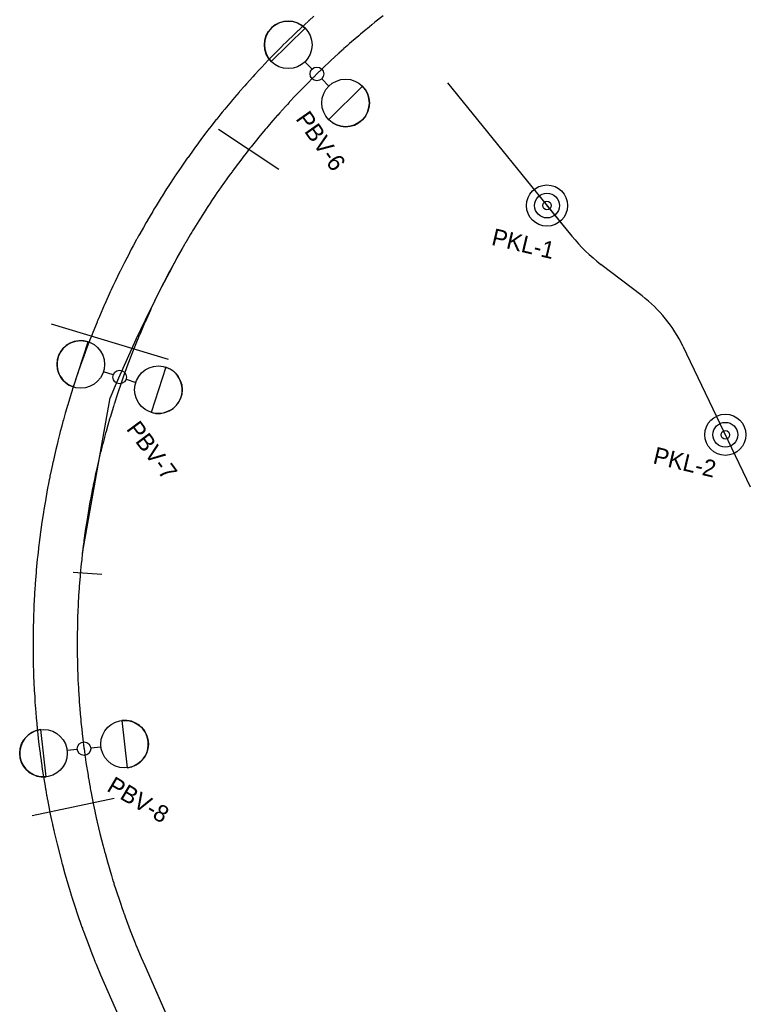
# Model space of a CAD drawing. Extents: x 0 to 511877, y 0 to 6211921.
# Drawn here: x 511553.8 to 511607.5, y 6211602.9 to 6211675.4 of the extents above; entities that cross this region are included whole.
import ezdxf

# ---------------------------------------------------------------- set-up
doc = ezdxf.new("R2010")
doc.units = 0
for name, color, linetype in [('Help', 7, 'Continuous'), ('TV_U_LYS_iWay', 7, 'Continuous'), ('TV_U_LYS_Ledn-', 7, 'Continuous'), ('TV_U_LYS_Ledn-ror', 7, 'Continuous'), ('TV_U_LYS_Mastenummer', 7, 'Continuous'), ('TV_U_LYS_Nyx330-Boligvej', 7, 'Continuous')]:
    doc.layers.add(name, color=color, linetype=linetype)

msp = doc.modelspace()

# ---------------------------------------------------------------- linework, layer by layer
at = {"layer": 'Help'}
for p, q in [((511585.237, 6211670.727), (511594.372, 6211659.463)), ((511568.38, 6211667.325), (511572.834, 6211664.395)), ((511556.075, 6211653.009), (511564.682, 6211650.411)), ((511602.55, 6211651.353), (511607.508, 6211641.01)), ((511557.697, 6211634.727), (511559.814, 6211634.593)), ((511554.669, 6211616.839), (511560.705, 6211618.102))]:
    msp.add_line(p, q, dxfattribs=at)
for points in [[(511575.406, 6211675.638), (511575.056, 6211675.322), (511575.042, 6211675.31), (511574.995, 6211675.268), (511574.469, 6211674.783), (511574.267, 6211674.594), (511574.219, 6211674.549), (511574.006, 6211674.346), (511573.83, 6211674.179), (511573.546, 6211673.904), (511573.506, 6211673.866), (511573.405, 6211673.767), (511573.104, 6211673.471), (511573.058, 6211673.426), (511572.617, 6211672.983), (511572.558, 6211672.923), (511572.405, 6211672.767), (511572.041, 6211672.392), (511571.827, 6211672.168), (511571.703, 6211672.037), (511571.665, 6211671.997), (511571.237, 6211671.539), (511571.199, 6211671.498), (511571.056, 6211671.343), (511570.915, 6211671.188), (511570.446, 6211670.668), (511570.315, 6211670.521), (511570.295, 6211670.498), (511569.942, 6211670.095), (511569.905, 6211670.053), (511569.566, 6211669.658), (511569.441, 6211669.511), (511569.414, 6211669.479), (511569.341, 6211669.393), (511568.844, 6211668.796), (511568.662, 6211668.574), (511568.56, 6211668.448), (511568.253, 6211668.066), (511568.226, 6211668.032), (511568.128, 6211667.908), (511567.85, 6211667.555), (511567.734, 6211667.405), (511567.708, 6211667.371), (511567.438, 6211667.02), (511567.087, 6211666.555), (511566.79, 6211666.156), (511566.762, 6211666.117), (511566.646, 6211665.958), (511566.623, 6211665.927), (511566.416, 6211665.641), (511566.119, 6211665.225), (511566.105, 6211665.205), (511566.092, 6211665.186), (511565.743, 6211664.687), (511565.592, 6211664.467), (511565.459, 6211664.273), (511565.132, 6211663.786), (511565.113, 6211663.758), (511565.112, 6211663.755), (511565.06, 6211663.678), (511564.837, 6211663.339), (511564.594, 6211662.964), (511564.571, 6211662.929), (511564.235, 6211662.399), (511564.176, 6211662.305), (511563.79, 6211661.68), (511563.702, 6211661.535), (511563.69, 6211661.515), (511563.639, 6211661.43), (511563.544, 6211661.272), (511563.17, 6211660.638), (511563.153, 6211660.609), (511563.064, 6211660.456), (511562.859, 6211660.099), (511562.588, 6211659.618), (511562.51, 6211659.477), (511562.373, 6211659.228), (511562.359, 6211659.203), (511562.104, 6211658.733), (511561.973, 6211658.488), (511561.841, 6211658.236), (511561.829, 6211658.214), (511561.631, 6211657.833), (511561.467, 6211657.513), (511561.449, 6211657.477), (511561.144, 6211656.868), (511561.131, 6211656.842), (511560.953, 6211656.478), (511560.775, 6211656.107), (511560.622, 6211655.783), (511560.614, 6211655.766), (511560.497, 6211655.515), (511560.47, 6211655.458), (511560.419, 6211655.348), (511560.016, 6211654.453), (511560.007, 6211654.433), (511560, 6211654.416), (511559.626, 6211653.548), (511559.573, 6211653.424), (511559.561, 6211653.394), (511559.51, 6211653.272), (511559.507, 6211653.266), (511559.471, 6211653.179), (511559.451, 6211653.131), (511559.138, 6211652.36), (511558.987, 6211651.977), (511558.98, 6211651.959), (511558.73, 6211651.307), (511558.601, 6211650.961), (511558.519, 6211650.739), (511558.511, 6211650.718), (511558.51, 6211650.715), (511558.496, 6211650.676), (511558.338, 6211650.237), (511558.073, 6211649.479), (511558.065, 6211649.456), (511557.97, 6211649.175), (511557.816, 6211648.709), (511557.681, 6211648.294), (511557.629, 6211648.13), (511557.626, 6211648.119), (511557.621, 6211648.103), (511557.552, 6211647.885), (511557.296, 6211647.041), (511557.262, 6211646.927), (511557.256, 6211646.908), (511557.118, 6211646.429), (511556.983, 6211645.95), (511556.945, 6211645.81), (511556.863, 6211645.507), (511556.856, 6211645.482), (511556.748, 6211645.074), (511556.69, 6211644.85), (511556.567, 6211644.364), (511556.561, 6211644.337), (511556.508, 6211644.122), (511556.42, 6211643.759), (511556.315, 6211643.31), (511556.213, 6211642.856), (511556.207, 6211642.828), (511556.169, 6211642.657), (511556.074, 6211642.216), (511555.989, 6211641.805), (511555.98, 6211641.762), (511555.976, 6211641.739), (511555.943, 6211641.577), (511555.939, 6211641.556), (511555.902, 6211641.367), (511555.791, 6211640.791), (511555.729, 6211640.452), (511555.68, 6211640.179), (511555.673, 6211640.139), (511555.559, 6211639.464), (511555.539, 6211639.342), (511555.538, 6211639.334), (511555.509, 6211639.152), (511555.502, 6211639.11), (511555.374, 6211638.264), (511555.367, 6211638.213), (511555.269, 6211637.497), (511555.262, 6211637.451), (511555.219, 6211637.114), (511555.216, 6211637.085), (511555.15, 6211636.535), (511555.145, 6211636.496), (511555.139, 6211636.438), (511555.09, 6211635.991), (511555.058, 6211635.692), (511554.981, 6211634.88), (511554.973, 6211634.788), (511554.97, 6211634.753), (511554.967, 6211634.711), (511554.903, 6211633.909), (511554.9, 6211633.86), (511554.891, 6211633.741), (511554.878, 6211633.543), (511554.853, 6211633.148), (511554.824, 6211632.622), (511554.81, 6211632.346), (511554.798, 6211632.091), (511554.796, 6211632.04), (511554.776, 6211631.497), (511554.769, 6211631.269), (511554.767, 6211631.218), (511554.753, 6211630.66), (511554.752, 6211630.597), (511554.748, 6211630.362), (511554.743, 6211629.96), (511554.741, 6211629.401), (511554.741, 6211629.347), (511554.741, 6211629.23), (511554.745, 6211628.718), (511554.746, 6211628.643), (511554.747, 6211628.591), (511554.755, 6211628.117), (511554.756, 6211628.053), (511554.763, 6211627.767), (511554.769, 6211627.573), (511554.789, 6211626.989), (511554.801, 6211626.711), (511554.803, 6211626.649), (511554.834, 6211626.04), (511554.837, 6211625.981), (511554.844, 6211625.854), (511554.864, 6211625.525), (511554.886, 6211625.199), (511554.907, 6211624.901), (511554.92, 6211624.724), (511554.975, 6211624.05), (511554.981, 6211623.981), (511555.014, 6211623.613), (511555.031, 6211623.437), (511555.037, 6211623.378), (511555.074, 6211623.013), (511555.094, 6211622.822), (511555.131, 6211622.486), (511555.181, 6211622.052), (511555.262, 6211621.405), (511555.267, 6211621.369), (511555.272, 6211621.33), (511555.335, 6211620.869), (511555.344, 6211620.803), (511555.384, 6211620.52), (511555.394, 6211620.457), (511555.426, 6211620.239), (511555.58, 6211619.262), (511555.601, 6211619.135), (511555.662, 6211618.782), (511555.674, 6211618.711), (511555.744, 6211618.323), (511555.756, 6211618.257), (511555.783, 6211618.11), (511555.794, 6211618.049), (511555.801, 6211618.011), (511556.013, 6211616.935), (511556.108, 6211616.479), (511556.169, 6211616.197), (511556.184, 6211616.13), (511556.196, 6211616.074), (511556.252, 6211615.826), (511556.256, 6211615.804), (511556.263, 6211615.773), (511556.271, 6211615.741), (511556.303, 6211615.599), (511556.51, 6211614.723), (511556.752, 6211613.766), (511556.783, 6211613.649), (511556.787, 6211613.631), (511556.801, 6211613.581), (511556.833, 6211613.459), (511556.867, 6211613.33), (511556.885, 6211613.265), (511556.903, 6211613.199), (511557.086, 6211612.537), (511557.397, 6211611.476), (511557.49, 6211611.172), (511557.498, 6211611.145), (511557.519, 6211611.079), (511557.52, 6211611.074), (511557.575, 6211610.897), (511557.591, 6211610.847), (511557.599, 6211610.821), (511557.741, 6211610.376), (511558.09, 6211609.328), (511558.236, 6211608.907), (511558.311, 6211608.694), (511558.337, 6211608.621), (511558.371, 6211608.526), (511558.378, 6211608.506), (511558.394, 6211608.461), (511558.403, 6211608.435), (511558.474, 6211608.239), (511558.86, 6211607.207), (511559.068, 6211606.673), (511559.218, 6211606.295), (511559.236, 6211606.25), (511559.25, 6211606.217), (511559.27, 6211606.168), (511559.277, 6211606.149), (511559.299, 6211606.095), (511559.381, 6211605.895), (511559.709, 6211605.111), (511559.982, 6211604.481), (511564.929, 6211593.23)], [(511580.498, 6211675.666), (511579.899, 6211675.191), (511579.665, 6211675.001), (511579.658, 6211674.995), (511579.483, 6211674.852), (511579.441, 6211674.818), (511579.135, 6211674.565), (511579.092, 6211674.529), (511578.843, 6211674.319), (511578.698, 6211674.197), (511578.168, 6211673.741), (511578.032, 6211673.622), (511577.842, 6211673.455), (511577.615, 6211673.253), (511577.576, 6211673.219), (511577.236, 6211672.913), (511577.228, 6211672.905), (511577.19, 6211672.87), (511576.681, 6211672.401), (511576.492, 6211672.224), (511576.45, 6211672.185), (511576.245, 6211671.991), (511576.081, 6211671.834), (511575.807, 6211671.57), (511575.773, 6211671.537), (511575.679, 6211671.446), (511575.388, 6211671.159), (511575.353, 6211671.124), (511574.925, 6211670.695), (511574.875, 6211670.645), (511574.732, 6211670.498), (511574.382, 6211670.138), (511574.18, 6211669.926), (511574.063, 6211669.803), (511574.033, 6211669.771), (511573.617, 6211669.326), (511573.587, 6211669.294), (511573.451, 6211669.145), (511573.321, 6211669.004), (511572.869, 6211668.502), (511572.748, 6211668.365), (511572.734, 6211668.35), (511572.391, 6211667.958), (511572.364, 6211667.928), (511572.036, 6211667.546), (511571.919, 6211667.409), (511571.895, 6211667.38), (511571.831, 6211667.305), (511571.351, 6211666.728), (511571.182, 6211666.521), (511571.088, 6211666.406), (511570.791, 6211666.036), (511570.77, 6211666.009), (511570.678, 6211665.894), (511570.411, 6211665.554), (511570.302, 6211665.413), (511570.281, 6211665.386), (511570.023, 6211665.051), (511569.689, 6211664.608), (511569.405, 6211664.226), (511569.383, 6211664.195), (511569.27, 6211664.041), (511569.253, 6211664.017), (511569.056, 6211663.745), (511568.769, 6211663.343), (511568.759, 6211663.329), (511568.751, 6211663.318), (511568.414, 6211662.835), (511568.273, 6211662.63), (511568.15, 6211662.45), (511567.833, 6211661.979), (511567.819, 6211661.958), (511567.818, 6211661.957), (511567.771, 6211661.886), (511567.558, 6211661.562), (511567.324, 6211661.201), (511567.31, 6211661.179), (511566.984, 6211660.665), (511566.936, 6211660.588), (511566.562, 6211659.983), (511566.482, 6211659.85), (511566.471, 6211659.834), (511566.423, 6211659.753), (511566.336, 6211659.609), (511565.973, 6211658.994), (511565.963, 6211658.976), (511565.879, 6211658.832), (511565.685, 6211658.493), (511565.424, 6211658.031), (511565.353, 6211657.903), (511565.221, 6211657.663), (511565.213, 6211657.648), (511564.966, 6211657.194), (511564.844, 6211656.965), (511564.717, 6211656.723), (511564.71, 6211656.71), (511564.52, 6211656.344), (511564.363, 6211656.037), (511564.351, 6211656.014), (511564.055, 6211655.422), (511564.049, 6211655.41), (511563.878, 6211655.06), (511563.709, 6211654.708), (511563.562, 6211654.398), (511563.557, 6211654.389), (511563.444, 6211654.145), (511563.42, 6211654.094), (511563.376, 6211653.999), (511562.985, 6211653.13), (511562.981, 6211653.122), (511562.979, 6211653.117), (511562.615, 6211652.274), (511562.569, 6211652.165), (511562.559, 6211652.139), (511562.509, 6211652.021), (511562.508, 6211652.018), (511562.473, 6211651.933), (511562.458, 6211651.898), (511562.155, 6211651.152), (511562.013, 6211650.79), (511562.011, 6211650.786), (511561.769, 6211650.156), (511561.648, 6211649.831), (511561.57, 6211649.619), (511561.564, 6211649.602), (511561.563, 6211649.599), (511561.551, 6211649.567), (511561.401, 6211649.151), (511561.145, 6211648.419), (511561.142, 6211648.41), (511561.051, 6211648.142), (511560.904, 6211647.698), (511560.776, 6211647.302), (511560.727, 6211647.148), (511560.725, 6211647.14), (511560.72, 6211647.126), (511560.657, 6211646.925), (511560.409, 6211646.109), (511560.38, 6211646.009), (511560.376, 6211645.997), (511560.243, 6211645.538), (511560.115, 6211645.08), (511560.08, 6211644.953), (511560, 6211644.661), (511559.996, 6211644.646), (511559.892, 6211644.252), (511559.839, 6211644.045), (511559.72, 6211643.575), (511559.716, 6211643.558), (511559.666, 6211643.354), (511559.583, 6211643.009), (511559.483, 6211642.582), (511559.385, 6211642.147), (511559.38, 6211642.128), (511559.345, 6211641.967), (511559.254, 6211641.545), (511559.173, 6211641.152), (511559.165, 6211641.115), (511559.161, 6211641.096), (511559.13, 6211640.939), (511559.127, 6211640.922), (511559.092, 6211640.746), (511558.986, 6211640.193), (511558.927, 6211639.873), (511558.881, 6211639.612), (511558.876, 6211639.586), (511558.765, 6211638.931), (511558.747, 6211638.821), (511558.746, 6211638.817), (511558.718, 6211638.64), (511558.714, 6211638.613), (511558.589, 6211637.79), (511558.585, 6211637.762), (511558.49, 6211637.065), (511558.486, 6211637.034), (511558.444, 6211636.707), (511558.442, 6211636.691), (511558.378, 6211636.156), (511558.374, 6211636.125), (511558.368, 6211636.075), (511558.321, 6211635.645), (511558.293, 6211635.371), (511558.218, 6211634.585), (511558.211, 6211634.506), (511558.208, 6211634.474), (511558.206, 6211634.443), (511558.144, 6211633.665), (511558.142, 6211633.629), (511558.134, 6211633.516), (511558.121, 6211633.33), (511558.097, 6211632.955), (511558.069, 6211632.451), (511558.056, 6211632.193), (511558.045, 6211631.949), (511558.044, 6211631.909), (511558.024, 6211631.385), (511558.017, 6211631.17), (511558.016, 6211631.131), (511558.003, 6211630.589), (511558.002, 6211630.538), (511557.998, 6211630.315), (511557.993, 6211629.934), (511557.991, 6211629.396), (511557.991, 6211629.352), (511557.991, 6211629.246), (511557.995, 6211628.75), (511557.996, 6211628.684), (511557.996, 6211628.641), (511558.004, 6211628.181), (511558.006, 6211628.128), (511558.012, 6211627.853), (511558.017, 6211627.675), (511558.037, 6211627.113), (511558.048, 6211626.851), (511558.05, 6211626.802), (511558.079, 6211626.21), (511558.082, 6211626.163), (511558.089, 6211626.044), (511558.108, 6211625.73), (511558.128, 6211625.421), (511558.148, 6211625.136), (511558.16, 6211624.977), (511558.213, 6211624.324), (511558.218, 6211624.271), (511558.25, 6211623.915), (511558.266, 6211623.75), (511558.271, 6211623.699), (511558.307, 6211623.347), (511558.325, 6211623.17), (511558.36, 6211622.852), (511558.408, 6211622.442), (511558.486, 6211621.818), (511558.49, 6211621.792), (511558.494, 6211621.76), (511558.554, 6211621.313), (511558.562, 6211621.258), (511558.601, 6211620.984), (511558.609, 6211620.929), (511558.639, 6211620.731), (511558.788, 6211619.784), (511558.806, 6211619.678), (511558.864, 6211619.336), (511558.875, 6211619.277), (511558.942, 6211618.901), (511558.952, 6211618.844), (511558.979, 6211618.702), (511558.989, 6211618.645), (511558.993, 6211618.623), (511559.198, 6211617.582), (511559.287, 6211617.156), (511559.345, 6211616.888), (511559.358, 6211616.827), (511559.37, 6211616.776), (511559.423, 6211616.536), (511559.427, 6211616.519), (511559.434, 6211616.489), (511559.44, 6211616.46), (511559.469, 6211616.333), (511559.667, 6211615.494), (511559.899, 6211614.577), (511559.926, 6211614.475), (511559.93, 6211614.459), (511559.942, 6211614.412), (511559.973, 6211614.296), (511560.006, 6211614.173), (511560.023, 6211614.112), (511560.038, 6211614.057), (511560.212, 6211613.427), (511560.511, 6211612.407), (511560.597, 6211612.126), (511560.603, 6211612.104), (511560.623, 6211612.04), (511560.624, 6211612.039), (511560.677, 6211611.867), (511560.692, 6211611.82), (511560.698, 6211611.802), (511560.831, 6211611.382), (511561.167, 6211610.374), (511561.303, 6211609.98), (511561.374, 6211609.779), (511561.398, 6211609.712), (511561.431, 6211609.621), (511561.437, 6211609.603), (511561.453, 6211609.56), (511561.461, 6211609.537), (511561.525, 6211609.36), (511561.897, 6211608.365), (511562.092, 6211607.864), (511562.235, 6211607.504), (511562.251, 6211607.465), (511562.263, 6211607.434), (511562.283, 6211607.387), (511562.289, 6211607.369), (511562.31, 6211607.319), (511562.385, 6211607.136), (511562.699, 6211606.384), (511562.96, 6211605.781), (511567.904, 6211594.538)]]:
    msp.add_lwpolyline(points, dxfattribs=at)
at = {"layer": 'TV_U_LYS_iWay'}
for centre, radius in [((511592.552, 6211661.707), 1.514), ((511592.552, 6211661.707), 0.914), ((511592.552, 6211661.707), 0.314), ((511605.672, 6211644.841), 1.514), ((511605.672, 6211644.841), 0.914), ((511605.672, 6211644.841), 0.314)]:
    msp.add_circle(centre, radius, dxfattribs=at)
at = {"layer": 'TV_U_LYS_Ledn-'}
for p, q in [((511592.522, 6211661.744), (511594.372, 6211659.463)), ((511599.542, 6211655.058), (511596.519, 6211657.374)), ((511602.55, 6211651.353), (511607.508, 6211641.01))]:
    msp.add_line(p, q, dxfattribs=at)
for points in [[(511580.498, 6211675.666), (511579.899, 6211675.191), (511579.665, 6211675.001), (511579.658, 6211674.995), (511579.483, 6211674.852), (511579.441, 6211674.818), (511579.135, 6211674.565), (511579.092, 6211674.529), (511578.843, 6211674.319), (511578.698, 6211674.197), (511578.168, 6211673.741), (511578.032, 6211673.622), (511577.842, 6211673.455), (511577.615, 6211673.253), (511577.576, 6211673.219), (511577.236, 6211672.913), (511577.228, 6211672.905), (511577.19, 6211672.87), (511576.681, 6211672.401), (511576.492, 6211672.224), (511576.45, 6211672.185), (511576.245, 6211671.991), (511576.081, 6211671.834), (511575.807, 6211671.57), (511575.773, 6211671.537), (511575.679, 6211671.446), (511575.388, 6211671.159), (511575.353, 6211671.124), (511574.925, 6211670.695), (511574.875, 6211670.645), (511574.732, 6211670.498), (511574.382, 6211670.138), (511574.18, 6211669.926), (511574.063, 6211669.803), (511574.033, 6211669.771), (511573.617, 6211669.326), (511573.587, 6211669.294), (511573.451, 6211669.145), (511573.321, 6211669.004), (511572.869, 6211668.502), (511572.748, 6211668.365), (511572.734, 6211668.35), (511572.391, 6211667.958), (511572.364, 6211667.928), (511572.036, 6211667.546), (511571.919, 6211667.409), (511571.895, 6211667.38), (511571.831, 6211667.305), (511571.351, 6211666.728), (511571.182, 6211666.521), (511571.088, 6211666.406), (511570.791, 6211666.036), (511570.77, 6211666.009), (511570.678, 6211665.894), (511570.411, 6211665.554), (511570.302, 6211665.413), (511570.281, 6211665.386), (511570.023, 6211665.051), (511569.689, 6211664.608), (511569.405, 6211664.226), (511569.383, 6211664.195), (511569.27, 6211664.041), (511569.253, 6211664.017), (511569.056, 6211663.745), (511568.769, 6211663.343), (511568.759, 6211663.329), (511568.751, 6211663.318), (511568.414, 6211662.835), (511568.273, 6211662.63), (511568.15, 6211662.45), (511567.833, 6211661.979), (511567.819, 6211661.958), (511567.818, 6211661.957), (511567.771, 6211661.886), (511567.558, 6211661.562), (511567.324, 6211661.201), (511567.31, 6211661.179), (511566.984, 6211660.665), (511566.936, 6211660.588), (511566.562, 6211659.983), (511566.482, 6211659.85), (511566.471, 6211659.834), (511566.423, 6211659.753), (511566.336, 6211659.609), (511565.973, 6211658.994), (511565.963, 6211658.976), (511565.879, 6211658.832)], [(511558.376, 6211636.141), (511558.374, 6211636.125), (511558.368, 6211636.075), (511558.321, 6211635.645), (511558.293, 6211635.371), (511558.218, 6211634.585), (511558.211, 6211634.506), (511558.208, 6211634.474), (511558.206, 6211634.443), (511558.144, 6211633.665), (511558.142, 6211633.629), (511558.134, 6211633.516), (511558.121, 6211633.33), (511558.097, 6211632.955), (511558.069, 6211632.451), (511558.056, 6211632.193), (511558.045, 6211631.949), (511558.044, 6211631.909), (511558.024, 6211631.385), (511558.017, 6211631.17), (511558.016, 6211631.131), (511558.003, 6211630.589), (511558.002, 6211630.538), (511557.998, 6211630.315), (511557.993, 6211629.934), (511557.991, 6211629.396), (511557.991, 6211629.352), (511557.991, 6211629.246), (511557.995, 6211628.75), (511557.996, 6211628.684), (511557.996, 6211628.641), (511558.004, 6211628.181), (511558.006, 6211628.128), (511558.012, 6211627.853), (511558.017, 6211627.675), (511558.037, 6211627.113), (511558.048, 6211626.851), (511558.05, 6211626.802), (511558.079, 6211626.21), (511558.082, 6211626.163), (511558.089, 6211626.044), (511558.108, 6211625.73), (511558.128, 6211625.421), (511558.148, 6211625.136), (511558.16, 6211624.977), (511558.213, 6211624.324), (511558.218, 6211624.271), (511558.25, 6211623.915), (511558.266, 6211623.75), (511558.271, 6211623.699), (511558.307, 6211623.347), (511558.325, 6211623.17), (511558.36, 6211622.852), (511558.408, 6211622.442), (511558.486, 6211621.818), (511558.49, 6211621.792), (511558.494, 6211621.76), (511558.554, 6211621.313), (511558.562, 6211621.258), (511558.601, 6211620.984), (511558.609, 6211620.929), (511558.639, 6211620.731), (511558.788, 6211619.784), (511558.806, 6211619.678), (511558.864, 6211619.336), (511558.875, 6211619.277), (511558.942, 6211618.901), (511558.952, 6211618.844), (511558.979, 6211618.702), (511558.989, 6211618.645), (511558.993, 6211618.623), (511559.198, 6211617.582), (511559.287, 6211617.156), (511559.345, 6211616.888), (511559.358, 6211616.827), (511559.37, 6211616.776), (511559.423, 6211616.536), (511559.427, 6211616.519), (511559.434, 6211616.489), (511559.44, 6211616.46), (511559.469, 6211616.333), (511559.667, 6211615.494), (511559.899, 6211614.577), (511559.926, 6211614.475), (511559.93, 6211614.459), (511559.942, 6211614.412), (511559.973, 6211614.296), (511560.006, 6211614.173), (511560.023, 6211614.112), (511560.038, 6211614.057), (511560.212, 6211613.427), (511560.511, 6211612.407), (511560.597, 6211612.126), (511560.603, 6211612.104), (511560.623, 6211612.04), (511560.624, 6211612.039), (511560.677, 6211611.867), (511560.692, 6211611.82), (511560.698, 6211611.802), (511560.831, 6211611.382), (511561.167, 6211610.374), (511561.303, 6211609.98), (511561.374, 6211609.779), (511561.398, 6211609.712), (511561.431, 6211609.621), (511561.437, 6211609.603), (511561.453, 6211609.56), (511561.461, 6211609.537), (511561.525, 6211609.36), (511561.897, 6211608.365), (511562.092, 6211607.864), (511562.235, 6211607.504), (511562.251, 6211607.465), (511562.263, 6211607.434), (511562.283, 6211607.387), (511562.289, 6211607.369), (511562.31, 6211607.319), (511562.385, 6211607.136), (511562.699, 6211606.384), (511562.96, 6211605.781), (511566.106, 6211598.628)]]:
    msp.add_lwpolyline(points, dxfattribs=at)
for centre, radius, start, end in [((511604.275, 6211667.494), 12.75, 219.04031, 232.53526), ((511658.605, 6211606.97), 106.244, 150.78119, 157.54573), ((511593.307, 6211646.922), 10.25, 25.61428, 52.53526)]:
    msp.add_arc(centre, radius, start, end, dxfattribs=at)
at = {"layer": 'TV_U_LYS_Ledn-ror'}
msp.add_line((511558.376, 6211636.141), (511560.416, 6211647.549), dxfattribs=at)
at = {"layer": 'TV_U_LYS_Nyx330-Boligvej'}
for p, q in [((511572.269, 6211672.301), (511574.762, 6211674.761)), ((511572.269, 6211672.301), (511572.269, 6211672.301)), ((511575.274, 6211671.749), (511574.747, 6211672.285)), ((511575.979, 6211671.038), (511576.506, 6211670.502)), ((511578.984, 6211670.486), (511576.491, 6211668.026)), ((511578.984, 6211670.486), (511578.984, 6211670.486)), ((511557.711, 6211648.356), (511558.8, 6211651.685)), ((511564.511, 6211649.819), (511563.422, 6211646.49)), ((511564.511, 6211649.819), (511564.511, 6211649.819)), ((511560.634, 6211649.242), (511559.921, 6211649.477)), ((511561.587, 6211648.933), (511562.301, 6211648.698)), ((511557.711, 6211648.356), (511557.711, 6211648.356)), ((511561.287, 6211623.82), (511561.676, 6211620.338)), ((511561.287, 6211623.82), (511561.287, 6211623.82)), ((511555.705, 6211619.669), (511555.316, 6211623.15)), ((511557.998, 6211621.688), (511557.252, 6211621.606)), ((511558.993, 6211621.801), (511559.74, 6211621.883)), ((511555.705, 6211619.669), (511555.705, 6211619.669))]:
    msp.add_line(p, q, dxfattribs=at)
for centre, radius in [((511573.516, 6211673.53), 1.75), ((511575.626, 6211671.393), 0.5), ((511575.626, 6211671.393), 0.5), ((511577.737, 6211669.257), 1.75), ((511558.256, 6211650.02), 1.75), ((511561.111, 6211649.087), 0.5), ((511561.111, 6211649.087), 0.5), ((511563.965, 6211648.155), 1.75), ((511561.48, 6211622.079), 1.75), ((511555.512, 6211621.41), 1.75), ((511558.496, 6211621.744), 0.5), ((511558.496, 6211621.744), 0.5)]:
    msp.add_circle(centre, radius, dxfattribs=at)
for centre, start, end in [((511573.516, 6211673.53), 44.65729, 224.58732), ((511577.737, 6211669.257), 224.65729, 44.58732), ((511558.256, 6211650.02), 71.91974, 251.84978), ((511563.965, 6211648.155), 251.91974, 71.84978), ((511561.48, 6211622.079), 276.40996, 96.33999), ((511555.512, 6211621.41), 96.40996, 276.33999)]:
    msp.add_arc(centre, 1.75, start, end, dxfattribs=at)

# ---------------------------------------------------------------- texts
at = {"layer": 'TV_U_LYS_Mastenummer'}
for s, rotation, p in [('PBV-6', 304.92449, (511574.019, 6211668.084)), ('PKL-1', 346.664, (511588.404, 6211658.828)), ('PBV-7', 306.5321, (511561.556, 6211645.257)), ('PKL-2', 346.664, (511600.283, 6211642.75)), ('PBV-8', 329.29476, (511560.095, 6211618.678))]:
    msp.add_text(s, height=1.25, rotation=rotation, dxfattribs=at).set_placement(p)

doc.saveas('drawing.dxf')
